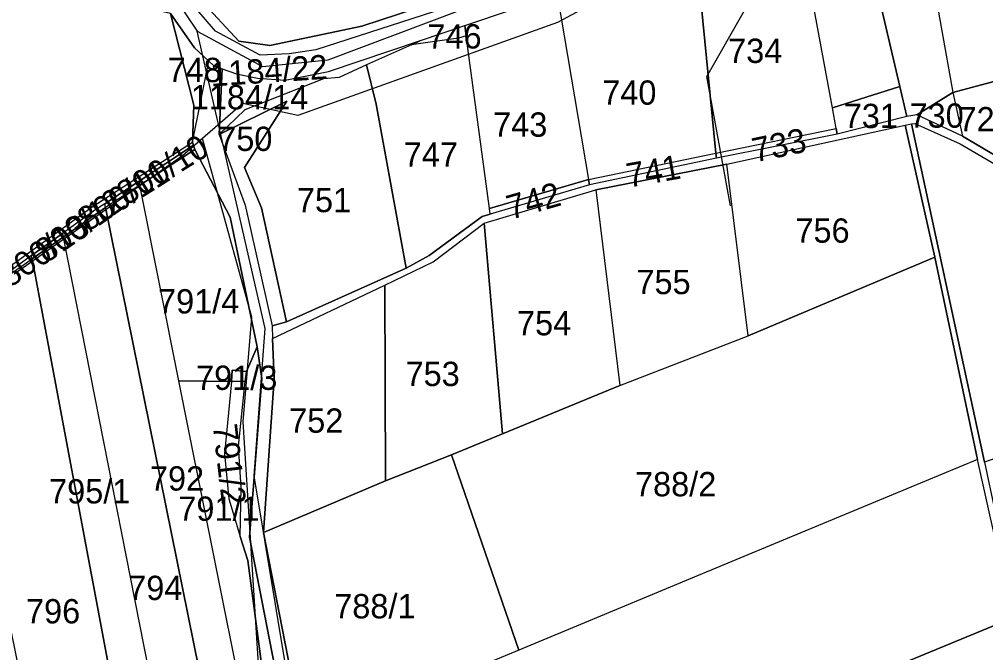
# Model space of a CAD drawing. Extents: x -623250 to -619626, y -1079612 to -1075424.
# Drawn here: x -621038.1 to -620640.4, y -1076996.3 to -1076735.6 of the extents above; entities that cross this region are included whole.
import ezdxf

# ---------------------------------------------------------------- set-up
doc = ezdxf.new("R2010")
doc.units = 0
for name, color, linetype in [('Cestní síť', 7, 'Continuous'), ('Parcela nároku', 7, 'Continuous'), ('Parcelní číslo', 7, 'Continuous'), ('Silnice III_35719', 7, 'Continuous'), ('Technická opateření liniová', 7, 'Continuous'), ('Vodní toky', 7, 'Continuous')]:
    doc.layers.add(name, color=color, linetype=linetype)

msp = doc.modelspace()

# ---------------------------------------------------------------- linework, layer by layer
at = {"layer": 'Cestní síť'}
for p, q in [((-620936.92, -1076862.87), (-620964.97, -1076740.51)), ((-620941.41, -1076923.5), (-620936.92, -1076862.87)), ((-620921.78, -1077041.94), (-620941.41, -1076923.5))]:
    msp.add_line(p, q, dxfattribs=at)
at = {"layer": 'Parcela nároku'}
for points in [[(-620630.85, -1076759.56), (-620652.12, -1076653.85), (-620672.93, -1076659.55), (-620653.89, -1076765.75)], [(-620698.1, -1076667.83), (-620672.93, -1076659.55), (-620653.89, -1076765.75), (-620668.72, -1076774.93), (-620672.84, -1076775.64), (-620675.77, -1076763.35)], [(-620947.75, -1076744.65), (-620935.01, -1076746.46), (-620897.2, -1076738.43), (-620836.73, -1076718.57), (-620813.61, -1076704.92), (-620740.47, -1076663.4), (-620740.54, -1076670.96), (-620749.09, -1076673.86), (-620795.29, -1076700.4), (-620817.76, -1076714.87), (-620836.66, -1076722.38), (-620916.14, -1076748.15), (-620927.05, -1076749.85), (-620938.92, -1076750.44), (-620957.4, -1076740.53), (-620967.47, -1076728.67), (-620963.55, -1076727.5)], [(-620698.1, -1076667.83), (-620675.77, -1076763.35), (-620703.52, -1076772.03), (-620717.48, -1076696.57), (-620722.32, -1076675.8)], [(-620963.55, -1076727.5), (-620787.66, -1076677.04), (-620813.61, -1076704.92), (-620836.73, -1076718.57), (-620897.2, -1076738.43), (-620935.01, -1076746.46), (-620947.75, -1076744.65)], [(-620703.52, -1076772.03), (-620717.48, -1076696.57), (-620758.37, -1076720.77), (-620751.44, -1076790.69), (-620701.95, -1076780.5)], [(-620758.37, -1076720.77), (-620769.69, -1076710.2), (-620777.86, -1076712.89), (-620784.36, -1076707.27), (-620816.8, -1076725.27), (-620803.87, -1076801.49), (-620751.44, -1076790.69)], [(-620816.8, -1076725.27), (-620803.87, -1076801.49), (-620844.59, -1076813.43), (-620854.16, -1076742.5), (-620854.74, -1076738.18)], [(-620966.25, -1076770.92), (-620966.87, -1076786.13), (-620960.13, -1076752.84), (-620966.03, -1076747.39), (-620975.87, -1076733.31)], [(-620873.05, -1076744.41), (-620854.74, -1076738.18), (-620854.16, -1076742.5), (-620857.36, -1076743.44), (-620876.71, -1076746.07)], [(-620857.36, -1076743.44), (-620876.71, -1076746.07), (-620895.17, -1076754.43), (-620891.21, -1076770.54), (-620878.84, -1076838.09), (-620869.42, -1076832.76), (-620847.59, -1076816.78), (-620844.27, -1076815.8), (-620844.59, -1076813.43), (-620854.16, -1076742.5)], [(-620910.83, -1076757.14), (-620873.05, -1076744.41), (-620876.71, -1076746.07), (-620895.17, -1076754.43), (-620906.53, -1076759.58), (-620912.96, -1076760.11), (-620945.33, -1076772.89), (-620955.92, -1076783.02), (-620954.58, -1076755.95), (-620948.79, -1076758.05), (-620940.1, -1076759.79), (-620928.75, -1076760.7)], [(-620912.96, -1076760.11), (-620945.33, -1076772.89), (-620955.92, -1076783.02), (-620927.97, -1076769.32), (-620945.44, -1076796.57), (-620938.37, -1076813.26), (-620928.08, -1076860.15), (-620878.84, -1076838.09), (-620891.21, -1076770.54), (-620895.17, -1076754.43), (-620906.53, -1076759.58)], [(-620630.85, -1076759.56), (-620653.89, -1076765.75), (-620649.92, -1076783.79), (-620622.54, -1076799.85)], [(-620703.52, -1076772.03), (-620675.77, -1076763.35), (-620672.84, -1076775.64), (-620701.5, -1076782.95), (-620701.95, -1076780.5)], [(-620653.89, -1076765.75), (-620649.92, -1076783.79), (-620668.72, -1076774.93)], [(-620938.37, -1076813.26), (-620945.44, -1076796.57), (-620927.97, -1076769.32), (-620955.92, -1076783.02), (-620945.19, -1076812.14), (-620934.09, -1076861.83), (-620928.08, -1076860.15)], [(-620673.49, -1076779.15), (-620661.33, -1076833.55), (-620738.17, -1076865.94), (-620747, -1076795.31)], [(-620623.15, -1076803.02), (-620601.05, -1076819.72), (-620582.67, -1076837.73), (-620562.89, -1076861.13), (-620549.06, -1076874.88), (-620567.8, -1076886.37), (-620607.58, -1076906.02), (-620640.94, -1076917.83), (-620670.91, -1076778.68), (-620669.62, -1076778.45), (-620650.89, -1076786.88)], [(-620751.44, -1076790.69), (-620701.95, -1076780.5), (-620701.5, -1076782.95), (-620751.23, -1076792.83)], [(-621137.46, -1076935.44), (-621136.45, -1076933.16), (-621132.46, -1076928.18), (-621126.16, -1076920.95), (-621116.71, -1076906.26), (-621078.85, -1076879.4), (-621066.72, -1076868.08), (-621042.72, -1076837.79), (-621038.82, -1076834.98), (-621007.66, -1076812.58), (-620966.87, -1076786.13), (-620966.47, -1076787.42), (-620988.84, -1076802.18), (-621002.96, -1076811.5), (-621006.67, -1076813.95), (-621020.36, -1076823.77), (-621033.06, -1076832.89), (-621041.87, -1076839.21), (-621065.58, -1076869.14), (-621077.55, -1076880.26), (-621103.2, -1076898.67), (-621115.37, -1076907.54), (-621124.9, -1076921.91)], [(-620966.47, -1076787.42), (-620965.91, -1076789.23), (-620988.51, -1076803.88), (-620988.84, -1076802.18)], [(-620951.31, -1076816.99), (-620940.19, -1076870.41), (-620944.66, -1076880.6), (-620950.44, -1076879.99), (-620950.76, -1076884.62), (-620972.42, -1076884.35), (-620988.51, -1076803.88), (-620965.91, -1076789.23)], [(-620803.87, -1076801.49), (-620751.44, -1076790.69), (-620751.23, -1076792.83), (-620803.48, -1076803.79)], [(-620738.17, -1076865.94), (-620747, -1076795.31), (-620800.82, -1076805.78), (-620790.98, -1076886.36)], [(-621002.96, -1076811.5), (-620988.84, -1076802.18), (-620988.51, -1076803.88), (-621002.65, -1076813.04)], [(-620803.87, -1076801.49), (-620803.48, -1076803.79), (-620844.27, -1076815.8), (-620844.59, -1076813.43)], [(-620972.42, -1076884.35), (-620988.51, -1076803.88), (-621002.65, -1076813.04), (-620979.97, -1076924.9), (-620957.34, -1077036.71), (-620943.82, -1077031.86), (-620945.19, -1077020.56)], [(-620800.82, -1076805.78), (-620790.98, -1076886.36), (-620839.21, -1076906.24), (-620846.76, -1076819.58)], [(-621002.65, -1076813.04), (-621002.96, -1076811.5), (-621006.67, -1076813.95), (-621020.36, -1076823.77), (-621020.06, -1076825.27)], [(-620939.41, -1077125.24), (-620957.34, -1077036.71), (-620979.97, -1076924.9), (-621002.65, -1076813.04), (-621020.06, -1076825.27), (-620983.2, -1077012.58), (-620960.16, -1077129.62), (-620951.82, -1077127.86)], [(-620867.74, -1076835.5), (-620846.76, -1076819.58), (-620839.21, -1076906.24), (-620860.19, -1076914.89), (-620887.44, -1076925.53), (-620887.7, -1076845)], [(-621020.36, -1076823.77), (-621020.06, -1076825.27), (-621032.81, -1076834.22), (-621033.06, -1076832.89)], [(-621032.81, -1076834.22), (-621020.06, -1076825.27), (-620983.2, -1077012.58), (-620999.81, -1077010.33)], [(-621041.87, -1076839.21), (-621065.58, -1076869.14), (-621065.15, -1076871.1), (-621040.87, -1076839.88), (-621032.81, -1076834.22), (-621033.06, -1076832.89)], [(-621040.87, -1076839.88), (-621032.81, -1076834.22), (-620999.81, -1077010.33), (-620977.01, -1077132.01), (-620978.48, -1077132.22), (-620998.5, -1077135.06), (-621009.6, -1077136.64), (-621010.77, -1077136.81), (-621038.05, -1077003.98), (-621065.15, -1076871.1)], [(-620661.33, -1076833.55), (-620643.85, -1076916.74), (-620738.29, -1076956.01), (-620832.54, -1076995.23), (-620860.19, -1076914.89), (-620839.21, -1076906.24), (-620790.98, -1076886.36), (-620738.17, -1076865.94)], [(-620933.89, -1076866.99), (-620887.7, -1076845), (-620887.44, -1076925.53), (-620937.66, -1076946.83), (-620933.24, -1076883.64)], [(-620945.17, -1076884.69), (-620944.66, -1076880.6), (-620940.19, -1076870.41), (-620938.3, -1076883.42), (-620943.44, -1076948.79), (-620925.77, -1077038.84), (-620912.07, -1077098.28), (-620924.65, -1077060.22), (-620937.66, -1077007.21), (-620944.07, -1076958.4), (-620947.15, -1076948.49), (-620946.76, -1076928.27), (-620947.86, -1076911.3)], [(-620607.58, -1076906.02), (-620640.94, -1076917.83), (-620636.67, -1076937.95), (-620566.06, -1076904), (-620535.32, -1076888.25), (-620549.06, -1076874.88), (-620567.8, -1076886.37)], [(-620950.44, -1076879.99), (-620944.66, -1076880.6), (-620945.17, -1076884.69), (-620950.76, -1076884.62)], [(-620951.9, -1076932.96), (-620947.15, -1076948.49), (-620944.07, -1076958.4), (-620937.66, -1077007.21), (-620945.19, -1077020.56), (-620972.42, -1076884.35), (-620950.76, -1076884.62), (-620953.69, -1076914.5)], [(-620950.76, -1076884.62), (-620953.69, -1076914.5), (-620951.9, -1076932.96), (-620947.15, -1076948.49), (-620946.76, -1076928.27), (-620947.86, -1076911.3), (-620945.17, -1076884.69)], [(-620860.19, -1076914.89), (-620832.54, -1076995.23), (-620921.02, -1077031.86), (-620937.66, -1076946.83), (-620887.44, -1076925.53)], [(-620629.28, -1076981.86), (-620643.85, -1076916.74), (-620738.29, -1076956.01), (-620832.54, -1076995.23), (-620921.02, -1077031.86), (-620904.58, -1077095.56), (-620767.08, -1077038.8)], [(-620767.08, -1077038.8), (-620904.58, -1077095.56), (-620896.8, -1077121.07), (-620760.56, -1077063.88), (-620624.13, -1077006.64), (-620629.28, -1076981.86)]]:
    msp.add_lwpolyline(points, close=True, dxfattribs=at)
for points in [[(-621038.82, -1076834.98), (-621007.66, -1076812.58), (-620966.87, -1076786.13), (-620966.25, -1076770.92), (-620975.87, -1076733.31), (-620983.82, -1076731.41), (-620992.68, -1076715.31), (-620994.45, -1076707.23), (-620997.65, -1076704.49), (-621005.46, -1076699.67), (-621020.64, -1076702.21), (-621049.01, -1076717.2)], [(-620836.66, -1076722.38), (-620916.14, -1076748.15), (-620927.05, -1076749.85), (-620938.92, -1076750.44), (-620957.4, -1076740.53), (-620967.47, -1076728.67)], [(-620975.87, -1076733.31), (-620966.03, -1076747.39), (-620960.13, -1076752.84), (-620958.17, -1076754.65), (-620954.58, -1076755.95), (-620948.79, -1076758.05), (-620940.1, -1076759.79), (-620928.75, -1076760.7), (-620910.83, -1076757.14), (-620873.05, -1076744.41), (-620854.74, -1076738.18), (-620816.8, -1076725.27)], [(-620925.77, -1077038.84), (-620943.44, -1076948.79), (-620938.3, -1076883.42), (-620940.19, -1076870.41), (-620951.31, -1076816.99), (-620965.91, -1076789.23), (-620966.47, -1076787.42), (-620966.87, -1076786.13), (-620960.13, -1076752.84), (-620958.17, -1076754.65), (-620954.58, -1076755.95), (-620955.92, -1076783.02), (-620945.19, -1076812.14), (-620934.09, -1076861.83), (-620933.89, -1076866.99), (-620933.24, -1076883.64), (-620937.66, -1076946.83), (-620921.02, -1077031.86)], [(-620622.54, -1076799.85), (-620649.92, -1076783.79), (-620668.72, -1076774.93), (-620672.84, -1076775.64), (-620701.5, -1076782.95), (-620751.23, -1076792.83), (-620803.48, -1076803.79), (-620844.27, -1076815.8), (-620847.59, -1076816.78), (-620869.42, -1076832.76), (-620878.84, -1076838.09), (-620928.08, -1076860.15), (-620934.09, -1076861.83), (-620933.89, -1076866.99), (-620887.7, -1076845), (-620867.74, -1076835.5), (-620846.76, -1076819.58), (-620800.82, -1076805.78), (-620747, -1076795.31), (-620673.49, -1076779.15), (-620670.91, -1076778.68), (-620669.62, -1076778.45), (-620650.89, -1076786.88), (-620623.15, -1076803.02)], [(-620629.28, -1076981.86), (-620643.85, -1076916.74), (-620661.33, -1076833.55), (-620673.49, -1076779.15), (-620670.91, -1076778.68), (-620640.94, -1076917.83), (-620636.67, -1076937.95)]]:
    msp.add_lwpolyline(points, dxfattribs=at)
at = {"layer": 'Silnice III_35719'}
for p, q in [((-620982.77, -1076713.8), (-620964.97, -1076740.51)), ((-620911.04, -1076752.31), (-620820.16, -1076718.07)), ((-620964.97, -1076740.51), (-620937.97, -1076755.12)), ((-620937.97, -1076755.12), (-620911.04, -1076752.31))]:
    msp.add_line(p, q, dxfattribs=at)
at = {"layer": 'Technická opateření liniová'}
for p, q in [((-620755.15, -1076759.14), (-620739.12, -1076731.07)), ((-620745.42, -1076812.41), (-620755.15, -1076759.14))]:
    msp.add_line(p, q, dxfattribs=at)
at = {"layer": 'Vodní toky'}
for p, q in [((-620766.03, -1076709.74), (-620816.68, -1076736.88)), ((-620816.68, -1076736.88), (-620910.48, -1076770.57)), ((-620946.11, -1076770.24), (-620970.95, -1076791.82)), ((-620923.47, -1076775.24), (-620946.11, -1076770.24)), ((-620910.48, -1076770.57), (-620923.47, -1076775.24)), ((-620942.37, -1076858.17), (-620962.75, -1076784.7)), ((-620970.95, -1076791.82), (-621040.23, -1076840.55)), ((-620945.97, -1076901.34), (-620942.37, -1076858.17)), ((-620938.8, -1077013.58), (-620945.97, -1076901.34))]:
    msp.add_line(p, q, dxfattribs=at)

# ---------------------------------------------------------------- texts
at = {"layer": 'Parcelní číslo'}
for s, p in [('746', (-620870.18, -1076747.66)), ('734', (-620746.42, -1076753.59)), ('748', (-620977.08, -1076761.48)), ('1184/14', (-620967.53, -1076772.7)), ('740', (-620798.23, -1076770.79)), ('731', (-620698.83, -1076780.41)), ('730', (-620671.76, -1076780.24)), ('725', (-620651.61, -1076781.75)), ('743', (-620843.13, -1076783.95)), ('750', (-620956.25, -1076789.81)), ('747', (-620879.92, -1076796.29)), ('751', (-620923.87, -1076815)), ('756', (-620718.72, -1076827.56)), ('755', (-620784.15, -1076848.73)), ('791/4', (-620981.02, -1076856.68)), ('754', (-620833.29, -1076865.67)), ('791/3', (-620965.36, -1076888.13)), ('753', (-620879.17, -1076886.56)), ('752', (-620927.07, -1076905.76)), ('792', (-620984.35, -1076929.56)), ('788/2', (-620784.74, -1076931.92)), ('795/1', (-621025.86, -1076934.86)), ('791/1', (-620972.67, -1076942)), ('794', (-620993.29, -1076974.6)), ('796', (-621035.36, -1076984.21)), ('788/1', (-620908.51, -1076982.13))]:
    msp.add_text(s, height=10, dxfattribs=at).set_placement(p)
for s, rotation, p in [('1184/22', 3.7815, (-620959.2, -1076763.29)), ('800/10', 31.8621, (-620993.94, -1076812.54)), ('733', 11.8615, (-620735.38, -1076794.57)), ('800/11', 32.2056, (-621010.05, -1076823.32)), ('741', 10.0302, (-620787.32, -1076804.95)), ('742', 15.9642, (-620835.88, -1076818.15)), ('800/12', 35.5554, (-621027.01, -1076836.3)), ('800/13', 34.2016, (-621042.12, -1076846.36)), ('791/2', 276.6808, (-620958.52, -1076902.67))]:
    msp.add_text(s, height=10, rotation=rotation, dxfattribs=at).set_placement(p)

doc.saveas('drawing.dxf')
